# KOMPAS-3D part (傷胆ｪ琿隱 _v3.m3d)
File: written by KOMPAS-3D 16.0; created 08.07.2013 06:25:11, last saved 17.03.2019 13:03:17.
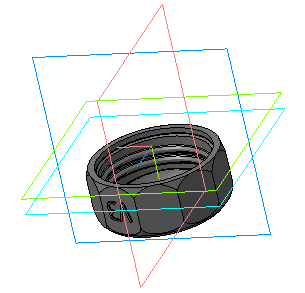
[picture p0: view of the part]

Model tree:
1. Эскиз:1
2. Операция вращения:1
     Угол 1 = 360
3. Эскиз:4
4. Параллельная плоскость:1
5. Эскиз:5
6. Спираль цилиндрическая:1
     Число витков = 2.125; Шаг = 2.7; Размер = 5.7375; Диаметр 1 = 10; Диаметр 2 = 10; Угол = 180
7. Кинематическая операция:1
     Толщина стенки 1 = 1; Толщина стенки 2 = 1
8. Фаска:1
     Угол = 73.3008; Длина 1 = 1.5; Длина 2 = 5
9. Фаска:2
     Угол = 69.444; Длина 1 = 1.5; Длина 2 = 4
10. Смещенная плоскость:1
     Расстояние = 4.25
11. Эскиз:7
12. Вырезать элемент выдавливания:2
     Расстояние 2 = 9.2; Расстояние 1 = 10
13. Эскиз:8
14. Операция выдавливания:1
     Расстояние 1 = 10.7
15. Массив по концентрической сетке:2  (with: Операция выдавливания:1)  (120 pattern instances)
     Шаг 2 = 360
16. Массив по концентрической сетке:3  (with: Вырезать элемент выдавливания:2, Смещенная плоскость:1)  (6 pattern instances)
     Геометрический массив = 5; Шаг 2 = 360
17. Эскиз:9
18. Операция вращения:3
     Угол 1 = 360
19. Эскиз:11
20. Вырезать элемент выдавливания:4
     Расстояние 1 = 10
21. Фаска:3
     Угол = 45; Длина 1 = 2; Длина 2 = 2
22. Фаска:4
     Угол = 71; Длина 1 = 0.8; Длина 2 = 2.32337
23. Скругление:2
     Радиус = 4
24. Эскиз:12
25. Вырезать элемент выдавливания:5
     Расстояние 1 = 20
26. Эскиз:13
27. Вырезать элемент вращения:1
     Угол 1 = 360
28. Эскиз:14
29. Операция вращения:4
     Угол 1 = 360
30. Эскиз:15
31. Операция выдавливания:2
     Расстояние 1 = 0.3
32. Фаска:6  (with: Сечение модели:1, Сечение модели:2)
     Угол = 75; Длина 1 = 1.05; Длина 2 = 3.91865

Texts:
  Точка начала. Х
  Точка начала. Y
  Точка начала. Z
